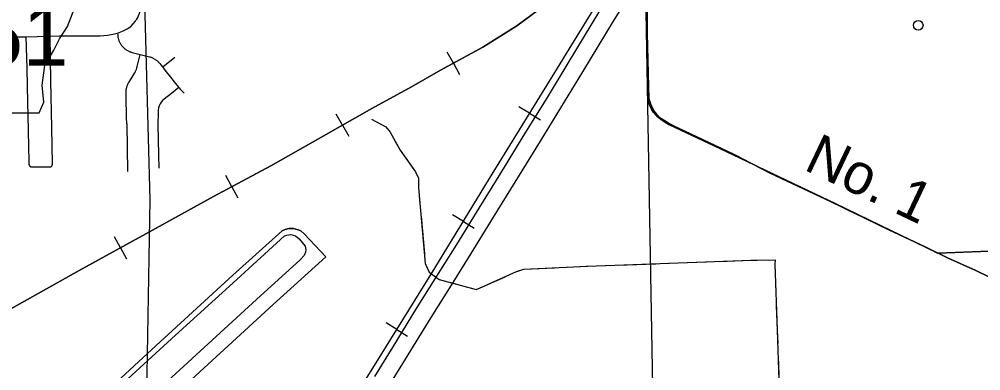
# Model space of a CAD drawing. Extents: x 646058 to 725608, y 1473014 to 1561048.
# Drawn here: x 651965 to 656968, y 1555679 to 1557507 of the extents above; entities that cross this region are included whole.
import ezdxf

# ---------------------------------------------------------------- set-up
doc = ezdxf.new("R2010")
doc.units = 0
doc.layers.add('Default', color=7, linetype='Continuous')

msp = doc.modelspace()

# ---------------------------------------------------------------- linework, layer by layer
at = {"layer": 'Default'}
for p, q in [((654223.7, 1557278.5), (654191.8, 1557336.3)), ((654223.7, 1557278.5), (654255.6, 1557220.7)), ((654620.4, 1557018.3), (654564.2, 1557052.8)), ((653647.2, 1556957.1), (653614.7, 1557014.6)), ((654620.4, 1557018.3), (654676.7, 1556983.7)), ((653647.2, 1556957.1), (653679.7, 1556899.7)), ((653070.6, 1556636.2), (653039.3, 1556694.3)), ((653070.6, 1556636.2), (653101.8, 1556578.1)), ((654275.8, 1556455.4), (654219.4, 1556489.8)), ((654275.8, 1556455.4), (654332.1, 1556421.1)), ((652491.8, 1556318.9), (652459.9, 1556376.7)), ((652491.8, 1556318.9), (652523.8, 1556261.1)), ((653929.8, 1555893.4), (653873.8, 1555928.2)), ((653929.8, 1555893.4), (653985.9, 1555858.6))]:
    msp.add_line(p, q, dxfattribs=at)
for points in [[(653580.6, 1555335.5), (653813.8, 1555706.5), (654109, 1556182), (654411.8, 1556678.7), (654737.4, 1557208.7), (655073.5, 1557753.8), (655286.9, 1558102.1), (655338.4, 1558192.9), (655371.7, 1558265.6), (655403.5, 1558341.3), (655438.3, 1558417), (655458, 1558461), (655509.8, 1558545.2), (655541, 1558600.6), (655634, 1558746.8), (655786.5, 1558996.6), (655895.8, 1559169.1), (655983.1, 1559325.2), (656092.3, 1559506.2), (656229.5, 1559731.1)], [(651118.9, 1555558.1), (651341.4, 1555682.3), (651819.8, 1555945.8), (652277.1, 1556200.2), (652693.4, 1556430.3), (652975, 1556584.8), (653273.3, 1556745.3), (653545.8, 1556899.8), (653800.2, 1557043.6), (654006.1, 1557155.7), (654157.5, 1557242), (654377, 1557363.1), (654554.2, 1557473.7), (654666.2, 1557556.9), (654755.5, 1557623.6), (654838.8, 1557693.2), (654931.2, 1557779.5), (655022, 1557873.4), (655134, 1557997.6), (655241.5, 1558132.4), (655303.6, 1558223.2), (655356.6, 1558308), (655458, 1558461)], [(651118.9, 1555558.1), (651341.4, 1555682.3), (651819.8, 1555945.8), (652277.1, 1556200.2), (652693.4, 1556430.3), (652975, 1556584.8), (653273.3, 1556745.3), (653545.8, 1556899.8), (653800.2, 1557043.6), (654006.1, 1557155.7), (654157.5, 1557242), (654377, 1557363.1), (654554.2, 1557473.7), (654666.2, 1557556.9), (654755.5, 1557623.6), (654838.8, 1557693.2), (654931.2, 1557779.5), (655022, 1557873.4), (655134, 1557997.6), (655241.5, 1558132.4), (655303.6, 1558223.2), (655356.6, 1558308), (655458, 1558461)], [(655458, 1558461), (655356.6, 1558308), (655303.6, 1558223.2), (655241.5, 1558132.4), (655134, 1557997.6), (655022, 1557873.4), (654931.2, 1557779.5), (654838.8, 1557693.2), (654755.5, 1557623.6), (654666.2, 1557556.9), (654554.2, 1557473.7), (654377, 1557363.1), (654157.5, 1557242), (654006.1, 1557155.7), (653800.2, 1557043.6), (653545.8, 1556899.8), (653273.3, 1556745.3), (652975, 1556584.8), (652693.4, 1556430.3), (652277.1, 1556200.2), (651819.8, 1555945.8), (651341.4, 1555682.3), (651118.9, 1555558.1)], [(653580.6, 1555335.5), (653813.8, 1555706.5), (654109, 1556182), (654411.8, 1556678.7), (654737.4, 1557208.7), (655073.5, 1557753.8), (655286.9, 1558102.1), (655338.4, 1558192.9), (655371.7, 1558265.6), (655403.5, 1558341.3), (655438.3, 1558417), (655458, 1558461)], [(653580.6, 1555335.5), (653813.8, 1555706.5), (654109, 1556182), (654411.8, 1556678.7), (654737.4, 1557208.7), (655073.5, 1557753.8), (655286.9, 1558102.1), (655338.4, 1558192.9), (655371.7, 1558265.6), (655403.5, 1558341.3), (655438.3, 1558417), (655458, 1558461)], [(655261.9, 1555594.5), (655214.5, 1558232.7)], [(652603.7, 1558110.8), (652645.2, 1556568.6), (652625.6, 1555461.7)], [(656743.7, 1556291.4), (656210.4, 1556549.1), (655409.7, 1556931), (655368.6, 1556947.3), (655342.9, 1556961.6), (655322.7, 1556973.8), (655305.3, 1556986), (655291.4, 1556996.1), (655279.5, 1557006.2), (655265.6, 1557022.2), (655255.2, 1557039), (655246.1, 1557057.1), (655239.8, 1557076.6), (655234.9, 1557096.9), (655216.5, 1558123.4)], [(655216.5, 1558123.4), (655234.9, 1557096.9), (655247.9, 1557053.4), (655252.2, 1557045), (655266, 1557021.7), (655282, 1557004.1), (655303.3, 1556987.4), (655315.4, 1556979), (655323.1, 1556973.5), (655345.8, 1556960), (655642.9, 1556819.7), (656007.4, 1556645.9), (656495.3, 1556411.4), (656706.1, 1556309.5), (656743.7, 1556291.4), (657011.2, 1556300.7)], [(652570, 1557497.8), (652574.2, 1557503.7), (652577.2, 1557508.2), (652581.3, 1557515.7), (652583.5, 1557520.3), (652585.6, 1557525), (652587.4, 1557529.8), (652589.2, 1557534.7), (652590.7, 1557539.6), (652592.2, 1557544.5), (652593.4, 1557549.5), (652594.9, 1557556.1), (652596.2, 1557562.7), (652597.3, 1557569.4), (652598.1, 1557576.1), (652598.7, 1557582.8), (652599.2, 1557589.6), (652599.4, 1557596.3), (652599.3, 1557603.1), (652599.1, 1557609.8), (652592.8, 1557919.9)], [(652570, 1557497.8), (652574.2, 1557503.7), (652577.2, 1557508.2), (652581.3, 1557515.7), (652583.5, 1557520.3), (652585.6, 1557525), (652587.4, 1557529.8), (652589.2, 1557534.7), (652590.7, 1557539.6), (652592.2, 1557544.5), (652593.4, 1557549.5), (652594.9, 1557556.1), (652596.2, 1557562.7), (652597.3, 1557569.4), (652598.1, 1557576.1), (652598.7, 1557582.8), (652599.2, 1557589.6), (652599.4, 1557596.3), (652599.3, 1557603.1), (652599.1, 1557609.8), (652592.8, 1557919.9)], [(653815.2, 1555649.7), (653909.8, 1555804.3), (654032.8, 1556003.9), (654138.5, 1556171.8), (654241.1, 1556335.9), (654358.3, 1556524.8), (654470.4, 1556706.7), (654601.7, 1556920.1), (654707.7, 1557092.4), (654821.6, 1557279.2), (654986.3, 1557551.8), (655096.3, 1557727), (655128.8, 1557780.1), (655181.1, 1557866.6), (655195.3, 1557887.1), (655196.1, 1557888.2), (655196.9, 1557889.2), (655197.7, 1557890.2), (655198.6, 1557891.2), (655199.5, 1557892.2), (655200.4, 1557893.1), (655211.1, 1557905.1), (655220.4, 1557908)], [(657085, 1556130.6), (656941.8, 1556200.2), (656795.3, 1556265.8), (656678.7, 1556324.1), (656489.3, 1556412.3), (656186.6, 1556558.8), (655872.6, 1556706.2), (655685.6, 1556803.3), (655487.3, 1556897.2), (655370, 1556953.1), (655338.4, 1556970.1), (655293.1, 1556998.4), (655267.2, 1557030.8), (655251.8, 1557064.8), (655240.5, 1557095.5), (655239.6, 1557157.1), (655232.4, 1557435.5), (655231.6, 1557590.9), (655234, 1557694.6), (655228.3, 1557833), (655229.1, 1557940.7), (655229, 1557942.2)], [(652690.8, 1553657.9), (654107.8, 1555957.2), (654213.4, 1556124.9), (654316.1, 1556289.2), (654433.5, 1556478.3), (654545.6, 1556660.4), (654677, 1556873.8), (654783, 1557046.2), (654897.1, 1557233.3), (655061.6, 1557505.5), (655230.6, 1557774.9)], [(655231.6, 1557590.9), (655232.4, 1557435.5), (655239.6, 1557157.1), (655240.5, 1557095.5), (655251.8, 1557064.8), (655267.2, 1557030.8), (655293.1, 1556998.4), (655338.4, 1556970.1), (655370, 1556953.1), (655487.3, 1556897.2), (655685.6, 1556803.3), (655872.6, 1556706.2), (656186.6, 1556558.8), (656489.3, 1556412.3), (656678.7, 1556324.1), (656795.3, 1556265.8), (656941.8, 1556200.2), (657085, 1556130.6)], [(651862.7, 1557414.3), (651924, 1557416), (652000.2, 1557416), (652174.6, 1557420.5), (652264, 1557420.5), (652385.4, 1557421.6), (652424.5, 1557423.8), (652451.3, 1557429.4), (652476.5, 1557435), (652502.8, 1557445.1), (652525.7, 1557457.4), (652545.3, 1557470.2), (652570, 1557497.8)], [(652280.9, 1557420.6), (652385.4, 1557421.6), (652424.5, 1557423.8), (652451.3, 1557429.4), (652476.5, 1557435), (652502.8, 1557445.1), (652525.7, 1557457.4), (652545.3, 1557470.2), (652570, 1557497.8)], [(655236.6, 1557274.1), (655232.4, 1557435.5), (655232.2, 1557472)], [(652000, 1557416), (652004.3, 1557251.2), (652007.9, 1557075.2), (652009.4, 1557006.6), (652014.4, 1556765.1), (652014.7, 1556756), (652014.7, 1556755.4), (652014.8, 1556754.8), (652014.8, 1556754.2), (652014.9, 1556753.6), (652015, 1556753), (652015.2, 1556752.4), (652015.3, 1556751.9), (652015.5, 1556751.3), (652015.7, 1556750.7), (652015.9, 1556750.2), (652016.1, 1556749.6), (652016.4, 1556749.1), (652016.6, 1556748.5), (652016.9, 1556748), (652017.2, 1556747.5), (652017.5, 1556747), (652017.9, 1556746.5), (652018.2, 1556746), (652018.6, 1556745.5), (652019, 1556745.1), (652019.4, 1556744.6), (652019.8, 1556744.2), (652020.2, 1556743.8), (652020.7, 1556743.4), (652021.1, 1556743), (652021.6, 1556742.7), (652022.1, 1556742.3), (652022.6, 1556742), (652023.1, 1556741.7), (652023.6, 1556741.4), (652024.1, 1556741.1), (652024.6, 1556740.8), (652025.2, 1556740.6), (652025.7, 1556740.3), (652026.3, 1556740.1), (652026.8, 1556740), (652027.4, 1556739.8), (652028, 1556739.6), (652028.6, 1556739.5), (652029.2, 1556739.4), (652077.7, 1556739.5)], [(652077.7, 1556739.5), (652120.8, 1556739.6), (652121.4, 1556739.5), (652122, 1556739.5), (652122.7, 1556739.5), (652123.3, 1556739.6), (652123.9, 1556739.6), (652124.6, 1556739.7), (652125.2, 1556739.8), (652125.8, 1556739.9), (652126.4, 1556740), (652127, 1556740.2), (652127.6, 1556740.3), (652128.2, 1556740.5), (652128.8, 1556740.7), (652129.4, 1556741), (652130, 1556741.2), (652130.6, 1556741.5), (652131.1, 1556741.8), (652131.7, 1556742.1), (652132.2, 1556742.4), (652132.7, 1556742.8), (652133.2, 1556743.2), (652133.7, 1556743.5), (652134.1, 1556744.1), (652134.5, 1556744.6), (652134.9, 1556745.2), (652135.2, 1556745.7), (652135.5, 1556746.3), (652135.9, 1556746.9), (652136.1, 1556747.5), (652136.4, 1556748.1), (652136.6, 1556748.7), (652136.9, 1556749.4), (652137.1, 1556750), (652137.2, 1556750.6), (652137.4, 1556751.3), (652137.5, 1556751.9), (652137.6, 1556752.6), (652137.7, 1556753.2), (652137.8, 1556753.9), (652137.9, 1556754.6), (652137.9, 1556755.2), (652137.9, 1556755.9), (652133.9, 1556944.3), (652130.1, 1557186.4), (652126.3, 1557419.2)], [(652477, 1557431.3), (652477.1, 1557428), (652477.3, 1557424.6), (652477.6, 1557421.3), (652478, 1557417.9), (652478.5, 1557414.6), (652479.2, 1557411.3), (652479.9, 1557408), (652480.8, 1557404.7), (652481.8, 1557401.5), (652482.8, 1557398.3), (652484, 1557395.2), (652485.3, 1557392.1), (652486.7, 1557389), (652488.3, 1557385.9), (652489.9, 1557382.9), (652491.6, 1557379.9), (652493.5, 1557377), (652495.4, 1557374.1), (652497.5, 1557371.3), (652499.6, 1557368.6), (652501.8, 1557366), (652504.2, 1557363.4), (652506.6, 1557361), (652509, 1557358.6), (652511.6, 1557356.3), (652514.3, 1557354.1), (652517, 1557351.9), (652519.8, 1557349.9), (652522.6, 1557348), (652525.6, 1557346.2), (652528.5, 1557344.4), (652531.6, 1557342.8), (652534.7, 1557341.3), (652537.6, 1557340), (652540.5, 1557338.8), (652543.5, 1557337.7), (652546.5, 1557336.7), (652549.5, 1557335.8), (652552.6, 1557334.9), (652594.5, 1557324.3)], [(652477, 1557431.3), (652477.1, 1557428), (652477.3, 1557424.6), (652477.6, 1557421.3), (652478, 1557417.9), (652478.5, 1557414.6), (652479.2, 1557411.3), (652479.9, 1557408), (652480.8, 1557404.7), (652481.8, 1557401.5), (652482.8, 1557398.3), (652484, 1557395.2), (652485.3, 1557392.1), (652486.7, 1557389), (652488.3, 1557385.9), (652489.9, 1557382.9), (652491.6, 1557379.9), (652493.5, 1557377), (652495.4, 1557374.1), (652497.5, 1557371.3), (652499.6, 1557368.6), (652501.8, 1557366), (652504.2, 1557363.4), (652506.6, 1557361), (652509, 1557358.6), (652511.6, 1557356.3), (652514.3, 1557354.1), (652517, 1557351.9), (652519.8, 1557349.9), (652522.6, 1557348), (652525.6, 1557346.2), (652528.5, 1557344.4), (652531.6, 1557342.8), (652534.7, 1557341.3), (652537.6, 1557340), (652540.5, 1557338.8), (652543.5, 1557337.7), (652546.5, 1557336.7), (652549.5, 1557335.8), (652552.6, 1557334.9), (652594.5, 1557324.3)], [(652524.8, 1556963.4), (652523.9, 1556998.5), (652523, 1557033.6), (652522, 1557068.6), (652521.1, 1557103.7), (652520.6, 1557123.9), (652520.6, 1557127.1), (652520.6, 1557130.3), (652520.8, 1557133.5), (652521.1, 1557136.7), (652521.4, 1557139.9), (652521.9, 1557143.1), (652522.5, 1557146.2), (652523.2, 1557149.4), (652524, 1557152.5), (652524.8, 1557155.6), (652525.8, 1557158.6), (652526.9, 1557161.6), (652528, 1557164.6), (652529.3, 1557167.6), (652530.7, 1557170.5), (652532.1, 1557173.3), (652533.6, 1557176.1), (652535.3, 1557178.9), (652546.7, 1557197.6), (652563, 1557224.2), (652565.9, 1557228.9), (652567.6, 1557231.9), (652569.2, 1557234.8), (652570.7, 1557237.8), (652572.1, 1557240.9), (652573.4, 1557244), (652574.5, 1557246.7), (652575.4, 1557249.5), (652575.7, 1557250.4), (652576.7, 1557253.6), (652577.6, 1557256.8), (652578.7, 1557261.2), (652594.5, 1557324.3)], [(652524.8, 1556963.4), (652523.9, 1556998.5), (652523, 1557033.6), (652522, 1557068.6), (652521.1, 1557103.7), (652520.6, 1557123.9), (652520.6, 1557127.1), (652520.6, 1557130.3), (652520.8, 1557133.5), (652521.1, 1557136.7), (652521.4, 1557139.9), (652521.9, 1557143.1), (652522.5, 1557146.2), (652523.2, 1557149.4), (652524, 1557152.5), (652524.8, 1557155.6), (652525.8, 1557158.6), (652526.9, 1557161.6), (652528, 1557164.6), (652529.3, 1557167.6), (652530.7, 1557170.5), (652532.1, 1557173.3), (652533.6, 1557176.1), (652535.3, 1557178.9), (652546.7, 1557197.6), (652563, 1557224.2), (652565.9, 1557228.9), (652567.6, 1557231.9), (652569.2, 1557234.8), (652570.7, 1557237.8), (652572.1, 1557240.9), (652573.4, 1557244), (652574.5, 1557246.7), (652575.4, 1557249.5), (652575.7, 1557250.4), (652576.7, 1557253.6), (652577.6, 1557256.8), (652578.7, 1557261.2), (652594.5, 1557324.3)], [(652594.5, 1557324.3), (652641.9, 1557312.4), (652645.2, 1557311.5), (652648.5, 1557310.5), (652651.7, 1557309.4), (652654.9, 1557308.2), (652658, 1557306.8), (652661.1, 1557305.4), (652664.1, 1557303.9), (652667.1, 1557302.2), (652670, 1557300.5), (652672.9, 1557298.7), (652675.7, 1557296.7), (652678.2, 1557294.8), (652680.7, 1557292.9), (652683.1, 1557290.9), (652685.5, 1557288.7), (652687.6, 1557286.7), (652689.7, 1557284.5), (652691.8, 1557282.3), (652693.8, 1557280.1), (652695.7, 1557277.8), (652701.4, 1557270.5), (652711.6, 1557257.7)], [(652594.5, 1557324.3), (652641.9, 1557312.4), (652645.2, 1557311.5), (652648.5, 1557310.5), (652651.7, 1557309.4), (652654.9, 1557308.2), (652658, 1557306.8), (652661.1, 1557305.4), (652664.1, 1557303.9), (652667.1, 1557302.2), (652670, 1557300.5), (652672.9, 1557298.7), (652675.7, 1557296.7), (652678.2, 1557294.8), (652680.7, 1557292.9), (652683.1, 1557290.9), (652685.5, 1557288.7), (652687.6, 1557286.7), (652689.7, 1557284.5), (652691.8, 1557282.3), (652693.8, 1557280.1), (652695.7, 1557277.8), (652701.4, 1557270.5), (652711.6, 1557257.7)], [(652774.1, 1557307.8), (652711.6, 1557257.7)], [(652774.1, 1557307.8), (652711.6, 1557257.7)], [(652711.6, 1557257.7), (652723.3, 1557243.1), (652752.8, 1557206.1), (652778.4, 1557174), (652794.3, 1557154), (652795.5, 1557152.5)], [(652711.6, 1557257.7), (652723.3, 1557243.1), (652752.8, 1557206.1), (652778.4, 1557174), (652794.3, 1557154), (652795.5, 1557152.5)], [(655276.7, 1557018.8), (655267.2, 1557030.8), (655251.8, 1557064.8), (655240.5, 1557095.5), (655239.6, 1557157.1), (655238.3, 1557208.1)], [(652795.5, 1557152.5), (652749, 1557115.2)], [(652795.5, 1557152.5), (652749, 1557115.2)], [(652795.5, 1557152.5), (652797.4, 1557150.2), (652802.2, 1557144.4), (652807.2, 1557138.8), (652812.4, 1557133.4), (652817.7, 1557128.1), (652823.2, 1557123)], [(652795.5, 1557152.5), (652797.4, 1557150.2), (652802.2, 1557144.4), (652807.2, 1557138.8), (652812.4, 1557133.4), (652817.7, 1557128.1), (652823.2, 1557123)], [(652749, 1557115.2), (652734.9, 1557104.1), (652718.5, 1557092.4), (652710.7, 1557084.7), (652704, 1557076.1), (652698.3, 1557066.8), (652693.7, 1557056.9), (652690.3, 1557046.5), (652688.1, 1557035.8), (652687.2, 1557024.9), (652686.3, 1556958.7), (652689.3, 1556801.8), (652691.3, 1556732.9)], [(652749, 1557115.2), (652734.9, 1557104.1), (652718.5, 1557092.4), (652710.7, 1557084.7), (652704, 1557076.1), (652698.3, 1557066.8), (652693.7, 1557056.9), (652690.3, 1557046.5), (652688.1, 1557035.8), (652687.2, 1557024.9), (652686.3, 1556958.7), (652689.3, 1556801.8), (652691.3, 1556732.9)], [(652524.8, 1556963.4), (652528.9, 1556716.4)], [(652524.8, 1556963.4), (652528.9, 1556716.4)], [(653797.8, 1556987.9), (653873, 1556948.7), (653894.3, 1556920.9), (653946.6, 1556826.1), (654026.6, 1556713.3), (654043, 1556680.6), (654043, 1556630), (654077.3, 1556237.7), (654098.5, 1556191.9), (654150.8, 1556154.3), (654342, 1556102), (654363.3, 1556110.2), (654552.8, 1556195.2), (654590.4, 1556208.2), (654922.1, 1556223), (655771.9, 1556254), (655897.7, 1556255.6), (655896.1, 1556234.4), (655909.2, 1555889.9), (655917.3, 1555630), (655921.6, 1555474.2)], [(655504.1, 1556889.3), (655487.3, 1556897.2), (655370, 1556953.1), (655338.4, 1556970.1), (655326.9, 1556977.3)], [(653919.1, 1556875.9), (653946.6, 1556826.1), (654026.6, 1556713.3), (654043, 1556680.6), (654043, 1556630), (654077.3, 1556237.7), (654098.5, 1556191.9), (654150.8, 1556154.3), (654342, 1556102), (654363.3, 1556110.2), (654552.8, 1556195.2), (654590.4, 1556208.2), (654922.1, 1556223), (655771.9, 1556254), (655897.7, 1556255.6), (655896.1, 1556234.4), (655909.2, 1555889.9), (655917.3, 1555630), (655921.6, 1555474.2)], [(653919.1, 1556875.9), (653946.6, 1556826.1), (653971, 1556791.7)], [(655741.7, 1556774.2), (655685.6, 1556803.3), (655563.7, 1556861)], [(655978, 1556656.7), (655872.6, 1556706.2), (655800.2, 1556743.8)], [(654009.2, 1556737.9), (654026.6, 1556713.3), (654043, 1556680.6), (654043, 1556630), (654050, 1556549.6)], [(656127.4, 1556586.6), (656037.8, 1556628.7)], [(656216.8, 1556544.2), (656186.6, 1556558.8), (656127.4, 1556586.6)], [(656454.5, 1556429.2), (656276.3, 1556515.4)], [(654055.7, 1556483.9), (654073, 1556286.6)], [(653077.1, 1556176.4), (653333.9, 1556406.8), (653347.9, 1556413.8), (653368.2, 1556419.1), (653391.9, 1556420), (653415.6, 1556412.9), (653429.7, 1556406.8), (653447.3, 1556391), (653559.8, 1556271.3), (653541.4, 1556254.6), (653286.4, 1556023.3)], [(653286.4, 1556023.3), (653541.4, 1556254.6), (653559.8, 1556271.3), (653447.3, 1556391), (653429.7, 1556406.8), (653415.6, 1556412.9), (653391.9, 1556420), (653368.2, 1556419.1), (653347.9, 1556413.8), (653333.9, 1556406.8), (653077.1, 1556176.4)], [(656693.3, 1556316.8), (656678.7, 1556324.1), (656514.1, 1556400.8)], [(653097.4, 1556153.5), (653344.4, 1556380.4), (653356.7, 1556384.8), (653378.7, 1556387.4), (653402.5, 1556381.3), (653420.9, 1556365.5), (653453.5, 1556326.8), (653457, 1556310), (653455.2, 1556296.9), (653448.2, 1556278.4), (653425.3, 1556254.6), (653219.6, 1556069.1)], [(653097.4, 1556153.5), (653344.4, 1556380.4), (653356.7, 1556384.8), (653378.7, 1556387.4), (653402.5, 1556381.3), (653420.9, 1556365.5), (653453.5, 1556326.8), (653457, 1556310), (653455.2, 1556296.9), (653448.2, 1556278.4), (653425.3, 1556254.6), (653219.6, 1556069.1)], [(665836.1, 1554301.5), (663213.3, 1554145.7), (660581.9, 1553971.7), (658595.4, 1553836.2), (658473.8, 1556351.9), (657879.5, 1556331.1), (656743.7, 1556291.4)], [(658473.8, 1556351.9), (658073.8, 1556337.9), (657713.6, 1556325.3), (657011.2, 1556300.7), (656792.7, 1556293.1)], [(655343.2, 1556238.3), (655541.1, 1556245.6)], [(655607.1, 1556248), (655771.9, 1556254), (655805, 1556254.4)], [(655870.9, 1556255.3), (655897.7, 1556255.6), (655896.1, 1556234.4), (655901.8, 1556084.6)], [(656932.2, 1556204.5), (656795.3, 1556265.8), (656752.4, 1556287.2)], [(654084.4, 1556222.4), (654098.5, 1556191.9), (654150.8, 1556154.3), (654247.2, 1556127.9)], [(654554, 1556195.6), (654590.4, 1556208.2), (654749.7, 1556215.3)], [(654815.6, 1556218.2), (654914.5, 1556222.6)], [(654914.5, 1556222.6), (654922.1, 1556223), (655013.5, 1556226.3)], [(655079.4, 1556228.7), (655277.3, 1556235.9)], [(652151.1, 1555327.8), (652356.1, 1555515), (652677.9, 1555810.5), (653077.1, 1556176.4)], [(653077.1, 1556176.4), (652677.9, 1555810.5), (652356.1, 1555515), (652151.1, 1555327.8)], [(653097.4, 1556153.5), (652777.3, 1555864.2), (652449.3, 1555562.5), (652415.9, 1555535.2), (652407.1, 1555516.8), (652404.5, 1555497.4), (652411.5, 1555478.1), (652425.6, 1555457.8), (652454.6, 1555427.1), (652474, 1555416.5), (652489.8, 1555415.6), (652507.4, 1555420), (652530.2, 1555437.6), (652737.7, 1555627.6), (653219.6, 1556069.1)], [(652434.3, 1555448.6), (652425.6, 1555457.8), (652411.5, 1555478.1), (652404.5, 1555497.4), (652407.1, 1555516.8), (652415.9, 1555535.2), (652449.3, 1555562.5), (652777.3, 1555864.2), (653097.4, 1556153.5)], [(654310.9, 1556110.5), (654342, 1556102), (654363.3, 1556110.2), (654493.7, 1556168.7)], [(653219.6, 1556069.1), (652737.7, 1555627.6), (652530.2, 1555437.6), (652507.4, 1555420), (652489.8, 1555415.6), (652474, 1555416.5), (652454.6, 1555427.1), (652434.3, 1555448.6)], [(652146.4, 1554983.1), (652755.3, 1555537.5), (653286.4, 1556023.3)], [(652146.4, 1554983.1), (652755.3, 1555537.5), (653286.4, 1556023.3)], [(655904.3, 1556018.6), (655909.2, 1555889.9), (655911.3, 1555820.8)], [(655913.4, 1555754.8), (655916.5, 1555655.8)]]:
    msp.add_lwpolyline(points, dxfattribs=at)
msp.add_lwpolyline([(651416.6, 1557815.9), (651454.7, 1557562.1), (651437.8, 1557177.3), (651471.6, 1557156.1), (651535, 1557156.1), (651535, 1557020.8), (652068, 1557020.8), (652093.3, 1557075.7), (652084.9, 1557164.6), (652097.6, 1557266.1), (652144.1, 1557346.4), (652173.7, 1557405.6), (652216, 1557469.1), (652241.4, 1557536.8), (652262.5, 1557591.7), (652300.6, 1557638.3), (652309, 1557667.9), (652292.1, 1557689), (652161, 1557689), (652190.6, 1557748.2), (652194.8, 1557786.3), (652177.3, 1557815.5)], close=True, dxfattribs=at)
msp.add_circle((656642.6, 1557476), 25, dxfattribs=at)

# ---------------------------------------------------------------- texts
msp.add_text('351', height=316.5, dxfattribs=at).set_placement((651513.4, 1557265.4))
msp.add_text('No. 1', height=211.2, rotation=334.5968, dxfattribs=at).set_placement((656041.2, 1556728))

doc.saveas('drawing.dxf')
